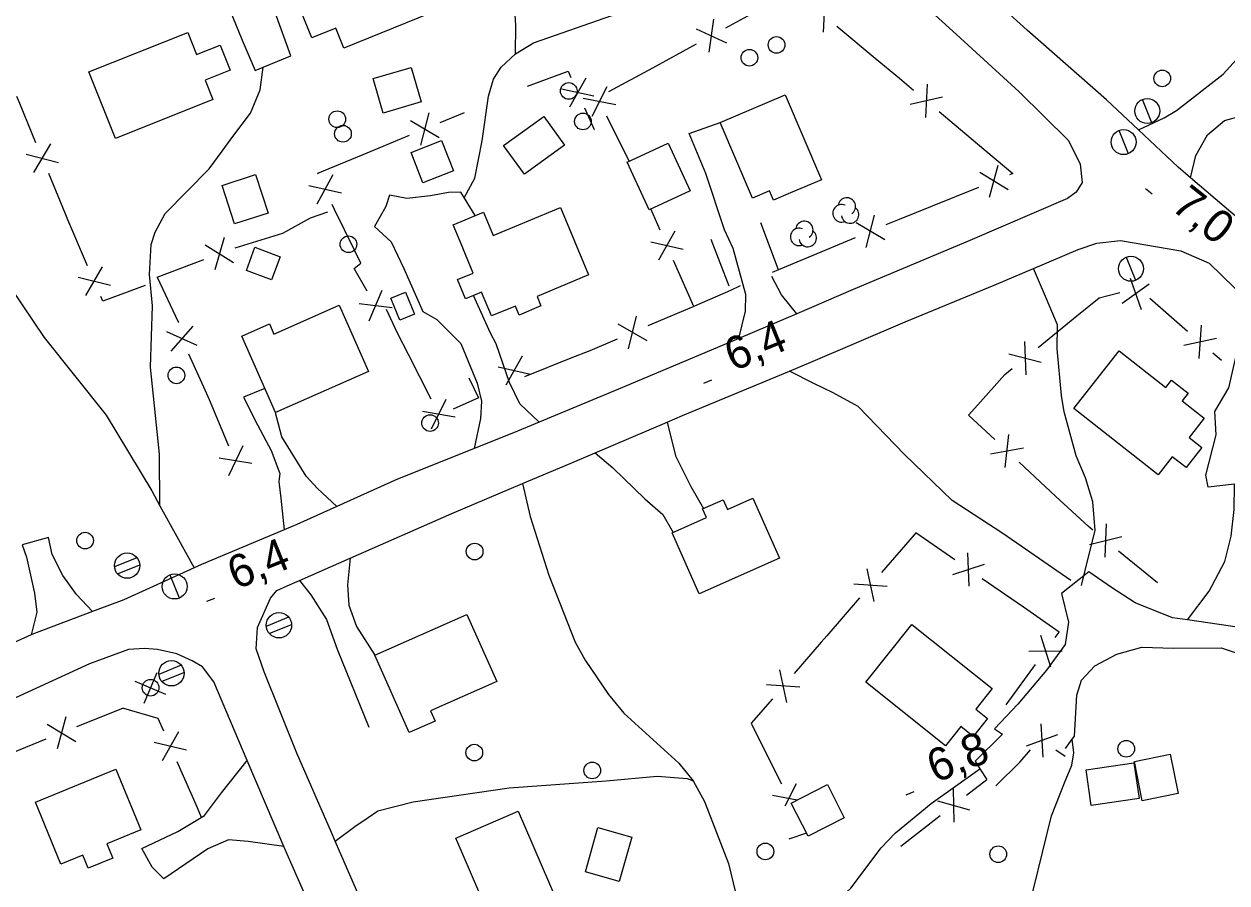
# Model space of a CAD drawing. Extents: x 362852 to 366875, y 5563573 to 5566479.
# Drawn here: x 364014.1 to 364158.5, y 5565067.1 to 5565170.1 of the extents above; entities that cross this region are included whole.
import ezdxf

# ---------------------------------------------------------------- set-up
doc = ezdxf.new("R2010")
doc.units = 0
for name, color, linetype in [('Niveau 19', 7, 'Continuous'), ('Niveau 21', 7, 'Continuous'), ('Niveau 22', 7, 'Continuous'), ('Niveau 3', 7, 'Continuous'), ('Niveau 31', 7, 'Continuous'), ('Niveau 36', 7, 'Continuous'), ('Niveau 37', 7, 'Continuous'), ('Niveau 44', 7, 'Continuous')]:
    doc.layers.add(name, color=color, linetype=linetype)

msp = doc.modelspace()

# ---------------------------------------------------------------- linework, layer by layer
at = {"layer": 'Niveau 19'}
for points in [[(364030.33, 5565182.91), (364033.16, 5565181.85), (364035.02, 5565180.58), (364036.29, 5565179.29), (364037.54, 5565176.67), (364038.08, 5565173.73), (364040.32, 5565168.2), (364041.86, 5565164.58), (364042.81, 5565164.97), (364046.13, 5565166.33), (364044.28, 5565171.52)], [(364147.84, 5565157.46), (364150.92, 5565158.88), (364152.41, 5565159.77), (364158.03, 5565164.14), (364160.41, 5565166.77)], [(364154.09, 5565151.71), (364154.75, 5565154.37), (364156.14, 5565156.85), (364158.19, 5565158.59), (364160.22, 5565159.12), (364161.65, 5565159.27), (364163.04, 5565160.49), (364160.62, 5565162.53), (364161.4, 5565163.35)], [(364099.9, 5565132.43), (364100.69, 5565135.69), (364100.74, 5565137.71), (364099.2, 5565143.21), (364098.16, 5565145.47), (364095.94, 5565152.23), (364093.92, 5565157), (364097.65, 5565158.33)], [(364068.25, 5565147.17), (364066.54, 5565149.97), (364065.06, 5565149.93), (364062.91, 5565149.54), (364060.08, 5565149.23), (364057.99, 5565149.62), (364057.54, 5565148.25), (364056.2, 5565145.86), (364058.2, 5565144.01), (364059.69, 5565140.81), (364061.99, 5565135.65), (364063.68, 5565134.72), (364066.54, 5565131.83), (364068.5, 5565127.09), (364069.01, 5565124.93), (364068.9, 5565122.85), (364068.14, 5565119.23)], [(364106.84, 5565135.4), (364105.01, 5565137.65), (364103.86, 5565139.87)], [(364075.94, 5565122.39), (364073.62, 5565124.6), (364072.38, 5565127.16), (364070.77, 5565131.78), (364070.11, 5565133.08), (364068.06, 5565137.58)], [(364169.24, 5565129.2), (364165.89, 5565127.7), (364164.45, 5565127.11), (364163.02, 5565125.65), (364162.19, 5565122.04), (364162.26, 5565114.76), (364160.28, 5565114.88), (364159.38, 5565114.94), (364156.21, 5565114.6), (364155.94, 5565116.04), (364157.16, 5565120.86), (364157.02, 5565123.67), (364158.71, 5565126.52), (364159.81, 5565131.4), (364160.53, 5565133.95), (364160.91, 5565137.04)], [(364043.03, 5565126.44), (364040.48, 5565125.38), (364042.14, 5565122.06), (364043.78, 5565119.01), (364044.83, 5565116.22), (364044.71, 5565115.29), (364044.93, 5565113.29), (364045.36, 5565109.48)], [(364051.66, 5565112.27), (364049.36, 5565114.45), (364047.98, 5565115.91), (364045.08, 5565120.64), (364044.25, 5565123.69)], [(364091.31, 5565122.4), (364092.31, 5565118.34), (364094.13, 5565114.68), (364095.65, 5565112.05)], [(364082.65, 5565118.71), (364084.78, 5565116.93), (364088.61, 5565113.22), (364090.77, 5565111.33), (364092, 5565109.18)], [(364022.36, 5565099.68), (364020.44, 5565101.74), (364018.78, 5565104), (364017.49, 5565106.54), (364017.05, 5565108.55), (364013.91, 5565107.69), (364014.43, 5565106.19), (364015.37, 5565101.88), (364015.66, 5565099.62), (364014.97, 5565096.89)], [(364053.26, 5565106.07), (364052.95, 5565102.87), (364053.09, 5565100.46), (364054.04, 5565097.88), (364056.22, 5565094.44)], [(364193.33, 5565090.24), (364190.98, 5565090.32), (364189.54, 5565090.65), (364186.03, 5565091.47), (364178.96, 5565093.7), (364173.42, 5565095.05), (364165.08, 5565096.96), (364158.89, 5565097.93), (364153.74, 5565098.68), (364151.93, 5565098.95), (364147.44, 5565100.71), (364144.63, 5565102.56), (364141.88, 5565104.43), (364138.6, 5565101.86), (364139.45, 5565098.43), (364139.06, 5565095.75), (364136.81, 5565092.65), (364133.37, 5565088.59), (364130.58, 5565085.63), (364131.54, 5565084.96), (364128.24, 5565081.73), (364128.82, 5565080.84), (364129.65, 5565079.56)], [(364047.2, 5565103.4), (364048.53, 5565101.69), (364050.43, 5565098.75), (364051.72, 5565095.19), (364055.49, 5565085.83)], [(364139.09, 5565083.25), (364139.88, 5565084.36), (364140.16, 5565084.75), (364140.46, 5565089.64), (364141.01, 5565091.46), (364142.62, 5565093.18), (364145.25, 5565094.56), (364148.27, 5565095.42), (364152.06, 5565095.29), (364157.76, 5565095.34), (364166.76, 5565092.34), (364180.59, 5565088.83), (364187.16, 5565086.77), (364189.66, 5565085.67), (364194.22, 5565083.12), (364197.22, 5565081.17)], [(364045.3, 5565071.49), (364041.03, 5565072.1), (364038.67, 5565072.3), (364036.18, 5565071.22), (364030.91, 5565067.62), (364029.51, 5565069.02), (364028.28, 5565071.27), (364032.59, 5565073.31), (364035.78, 5565075.21), (364037.81, 5565077.95), (364040.9, 5565081.84)]]:
    msp.add_lwpolyline(points, dxfattribs=at)
at = {"layer": 'Niveau 21'}
for points in [[(364117.4, 5565176.73), (364126.01, 5565168.87), (364133.53, 5565162.01), (364139.44, 5565156.18), (364140.85, 5565153.32), (364141.1, 5565151.14), (364140.38, 5565149.97), (364139.32, 5565149.22), (364127.62, 5565144.2), (364113.6, 5565138.3), (364106.84, 5565135.4), (364099.9, 5565132.43), (364085.93, 5565126.54), (364075.94, 5565122.39), (364072.87, 5565121.12), (364058.94, 5565115.56), (364051.66, 5565112.27), (364046.88, 5565110.11), (364045.36, 5565109.48), (364035.44, 5565105.33), (364034.56, 5565104.93), (364026.1, 5565101.09), (364022.36, 5565099.68), (364015.07, 5565096.94), (364014.97, 5565096.89)], [(364161.9, 5565145.07), (364154.09, 5565151.71), (364152.6, 5565152.98), (364147.84, 5565157.46), (364144.01, 5565161.06), (364134.51, 5565169.42), (364126.91, 5565176.33)], [(364047.2, 5565103.4), (364053.26, 5565106.07), (364065.45, 5565111.44), (364073.94, 5565115.02), (364079.68, 5565117.44), (364082.65, 5565118.71), (364091.31, 5565122.4), (364093.15, 5565123.18), (364105.98, 5565128.53), (364108.53, 5565129.59), (364119.85, 5565134.42), (364130.54, 5565138.84), (364135.26, 5565140.83), (364140.6, 5565143.09), (364142.84, 5565143.88), (364145.71, 5565144.18), (364152.93, 5565142.95), (364156.34, 5565141.47), (364160.91, 5565137.04)], [(364076.64, 5565013.12), (364074.62, 5565017.79), (364070.1, 5565028.61), (364065.41, 5565040.22), (364061.55, 5565049.19), (364059.97, 5565052.86), (364057.47, 5565058.45), (364055.09, 5565063.79), (364051.48, 5565072.13), (364051.02, 5565073.18), (364046.88, 5565082.7), (364042.96, 5565092.44), (364041.99, 5565095.2), (364042.14, 5565097.76), (364043.7, 5565101.27), (364044.45, 5565102.2), (364045.71, 5565102.78), (364047.2, 5565103.4)], [(364014.97, 5565096.89), (364004.58, 5565092.2), (363993.89, 5565087.69), (363989.6, 5565085.91), (363982.47, 5565082.95), (363972.35, 5565078.72), (363969.55, 5565077.55), (363966.87, 5565076.45), (363954.9, 5565071.52), (363942.22, 5565066.06), (363940.98, 5565065.54), (363935.86, 5565063.39), (363928.42, 5565060.25), (363915.63, 5565054.66), (363903.7, 5565049.52), (363899.8, 5565047.93), (363890.84, 5565044.27), (363888.1, 5565044.09), (363885.47, 5565045.51), (363884.66, 5565046.43), (363883.7, 5565047.85)], [(364070.9, 5565011.01), (364067.4, 5565020.3), (364061.76, 5565033.41), (364059.17, 5565039.33), (364056.61, 5565045.17), (364051.68, 5565057.14), (364048.11, 5565065.15), (364045.85, 5565070.21), (364045.3, 5565071.49), (364040.9, 5565081.84), (364036.89, 5565091.26), (364035.53, 5565093.07), (364034.32, 5565093.76), (364032.47, 5565094.63), (364030.15, 5565095.12), (364028.6, 5565095.24), (364026.65, 5565095.13), (364021.99, 5565093.4), (364010.11, 5565087.96)]]:
    msp.add_lwpolyline(points, dxfattribs=at)
at = {"layer": 'Niveau 22'}
for points in [[(364073.11, 5565166.57), (364073.14, 5565170.02), (364072.77, 5565175.59), (364071.71, 5565179.29), (364067.79, 5565187.16), (364064.84, 5565192.28), (364063.77, 5565193.53), (364061.43, 5565195.61)], [(364066.96, 5565149.28), (364068.23, 5565151.67), (364069.09, 5565156.15), (364069.87, 5565161.48), (364070.47, 5565163.54), (364071.38, 5565164.98), (364073.11, 5565166.57), (364075.26, 5565167.88), (364084.68, 5565171.15), (364087.7, 5565173.39), (364090.41, 5565175.63)], [(363993.59, 5565168.04), (363995.67, 5565166.21), (363997.93, 5565161.8), (363998.93, 5565159.96), (364005.68, 5565149.03), (364011.28, 5565140.4), (364016.53, 5565132.54), (364024, 5565123.22), (364029.46, 5565114.17), (364030.44, 5565112.37), (364032.47, 5565108.67), (364034.56, 5565104.93)], [(364030.44, 5565112.37), (364030.4, 5565118.54), (364029.3, 5565129), (364029.55, 5565136.36), (364029.18, 5565140.12), (364029.4, 5565143.72), (364029.87, 5565145.16), (364031.08, 5565147.41), (364036.33, 5565152.76), (364037.89, 5565154.9), (364039.2, 5565156.66), (364041.3, 5565159.45), (364042.48, 5565162.25), (364042.81, 5565164.97)], [(364141.03, 5565102.8), (364141.84, 5565106.23), (364142.66, 5565109.39), (364142.38, 5565112.84), (364141.5, 5565115.73), (364140.38, 5565118.37), (364138.92, 5565123.62), (364138.61, 5565125.61), (364138.08, 5565131.18), (364138.15, 5565134.08), (364136.7, 5565137.46), (364135.26, 5565140.83)], [(364139.73, 5565103.42), (364131.57, 5565109.04), (364125.49, 5565113.02), (364119.78, 5565118.5), (364114.22, 5565124.26), (364111.21, 5565125.93), (364108.89, 5565127.04), (364105.98, 5565128.53)], [(364073.94, 5565115.02), (364074.85, 5565111.09), (364077.11, 5565104.04), (364080.28, 5565096), (364081.46, 5565093.86), (364084.25, 5565089.75), (364086.1, 5565087.51), (364092.68, 5565081.49), (364094.4, 5565079.39), (364095.79, 5565076.89), (364098.65, 5565069.47), (364100.61, 5565061.36), (364100.88, 5565060.77), (364104.18, 5565053.64), (364107.33, 5565048.66), (364107.97, 5565047.65), (364111.46, 5565044.94)], [(364153.74, 5565098.68), (364156.34, 5565102.11), (364158.22, 5565105.67), (364158.98, 5565108.73), (364159.33, 5565111.94), (364159.38, 5565114.94)], [(364133.23, 5565059.43), (364135.27, 5565066.38), (364137.4, 5565075.17), (364138.97, 5565079.16), (364139.86, 5565081.28), (364140.08, 5565082.74), (364139.88, 5565084.36)], [(364100.88, 5565060.77), (364102.92, 5565060.75), (364104.96, 5565061.08), (364108.25, 5565062.41), (364110.46, 5565063.88), (364113.33, 5565066.53), (364116.98, 5565071.34), (364118.71, 5565073.14), (364122.98, 5565076.67), (364128.82, 5565080.84)], [(364051.48, 5565072.13), (364053.81, 5565073.92), (364055.41, 5565074.97), (364056.59, 5565075.77), (364060.84, 5565076.86), (364072.34, 5565078.55), (364084, 5565079.37), (364090.09, 5565079.95), (364093.69, 5565079.68), (364094.4, 5565079.39)]]:
    msp.add_lwpolyline(points, dxfattribs=at)
at = {"layer": 'Niveau 3'}
for p, q in [((364148.68, 5565150.41), (364149.5, 5565149.76)), ((364095.68, 5565127.08), (364096.66, 5565127.47)), ((364036.05, 5565100.91), (364037.01, 5565101.3)), ((364119.98, 5565077.72), (364120.94, 5565078.11))]:
    msp.add_line(p, q, dxfattribs=at)
at = {"layer": 'Niveau 31'}
for points in [[(364050.22, 5565172.88), (364049.25, 5565175.25), (364061.1, 5565180.05), (364064.35, 5565172.03), (364052.51, 5565167.24), (364051.53, 5565169.64), (364048.65, 5565168.48), (364047.34, 5565171.71), (364050.22, 5565172.88)], [(364035.87, 5565163.4), (364036.79, 5565161.09), (364025.09, 5565156.42), (364021.9, 5565164.4), (364033.77, 5565169.14), (364034.84, 5565166.47), (364037.67, 5565167.6), (364038.87, 5565164.6), (364035.87, 5565163.4)], [(364061.78, 5565160.79), (364057.23, 5565159.47), (364056.02, 5565163.6), (364060.57, 5565164.92), (364061.78, 5565160.79)], [(364097.65, 5565158.33), (364105.45, 5565161.66), (364109.8, 5565151.47), (364106.1, 5565149.89), (364104.07, 5565149.03), (364103.59, 5565150.14), (364101.52, 5565149.26), (364097.65, 5565158.33)], [(364078.99, 5565155.6), (364074.17, 5565152.12), (364071.67, 5565155.59), (364076.49, 5565159.07), (364078.99, 5565155.6)], [(364064.24, 5565156.17), (364065.66, 5565152.52), (364061.99, 5565151.1), (364060.58, 5565154.75), (364064.24, 5565156.17)], [(364091.41, 5565155.85), (364094.04, 5565150.13), (364089.12, 5565147.86), (364086.48, 5565153.58), (364091.41, 5565155.85)], [(364041.92, 5565152.08), (364043.42, 5565147.47), (364039.4, 5565146.16), (364037.9, 5565150.77), (364041.92, 5565152.08)], [(364068.04, 5565140.28), (364066.82, 5565143.19), (364066.78, 5565143.3), (364065.62, 5565146.07), (364069.25, 5565147.58), (364070.43, 5565144.76), (364078.5, 5565148.14), (364081.88, 5565140.05), (364075.69, 5565137.46), (364076.16, 5565136.33), (364073.55, 5565135.24), (364073.1, 5565136.32), (364070.24, 5565135.13), (364069.04, 5565137.99), (364067.12, 5565137.19), (364066.16, 5565139.49), (364068.04, 5565140.28)], [(364040.81, 5565140.6), (364041.84, 5565143.37), (364044.86, 5565142.24), (364043.83, 5565139.47), (364040.81, 5565140.6)], [(364058.15, 5565137.26), (364059.92, 5565137.98), (364060.99, 5565135.36), (364059.22, 5565134.64), (364058.15, 5565137.26)], [(364044.12, 5565132.94), (364051.95, 5565136.41), (364055.45, 5565128.49), (364044.3, 5565123.56), (364040.26, 5565132.7), (364043.57, 5565134.17), (364044.12, 5565132.94)], [(364150.2, 5565116.09), (364140.1, 5565124.02), (364145.52, 5565130.94), (364151.13, 5565126.54), (364151.83, 5565127.44), (364153.82, 5565125.88), (364153.1, 5565124.97), (364155.75, 5565122.89), (364153.93, 5565120.56), (364155.45, 5565119.36), (364153.56, 5565116.95), (364151.91, 5565118.25), (364150.2, 5565116.09)], [(364104.77, 5565106.08), (364095.13, 5565101.81), (364091.88, 5565109.13), (364096.01, 5565110.96), (364095.54, 5565112.01), (364098, 5565113.09), (364098.52, 5565111.92), (364101.58, 5565113.28), (364104.77, 5565106.08)], [(364063.45, 5565086.54), (364060.34, 5565085.16), (364056.22, 5565094.44), (364067.27, 5565099.34), (364070.85, 5565091.29), (364062.91, 5565087.76), (364063.45, 5565086.54)], [(364126.52, 5565085.89), (364124.69, 5565083.6), (364115.13, 5565091.23), (364120.64, 5565098.14), (364130.28, 5565090.45), (364128.32, 5565087.99), (364129.73, 5565086.86), (364128.01, 5565084.7), (364126.52, 5565085.89)], [(364151.66, 5565082.58), (364152.62, 5565077.85), (364148.31, 5565076.97), (364147.36, 5565081.7), (364151.66, 5565082.58)], [(364015.49, 5565076.83), (364025.15, 5565080.79), (364028.14, 5565073.49), (364024.07, 5565071.82), (364024.77, 5565070.12), (364021.81, 5565068.91), (364021.17, 5565070.45), (364018.55, 5565069.38), (364015.49, 5565076.83)], [(364141.57, 5565080.72), (364147.3, 5565081.55), (364147.92, 5565077.26), (364142.19, 5565076.43), (364141.57, 5565080.72)], [(364106.17, 5565076.7), (364110.52, 5565078.93), (364112.54, 5565074.96), (364108.2, 5565072.74), (364106.17, 5565076.7)], [(364071.45, 5565059.7), (364065.93, 5565072.51), (364073.43, 5565075.74), (364078.93, 5565062.96), (364077.14, 5565062.19), (364077.85, 5565060.53), (364075.01, 5565059.31), (364074.31, 5565060.94), (364071.45, 5565059.7)], [(364087.06, 5565072.63), (364085.55, 5565067.33), (364081.49, 5565068.49), (364083, 5565073.79), (364087.06, 5565072.63)]]:
    msp.add_lwpolyline(points, dxfattribs=at)
at = {"layer": 'Niveau 36'}
for p, q in [((364149.47, 5565158.3), (364148.35, 5565161.08)), ((364146.64, 5565154.58), (364145.52, 5565157.36)), ((364147.52, 5565139.37), (364146.4, 5565142.15)), ((364027.67, 5565106.13), (364024.99, 5565105.04)), ((364025.33, 5565104.19), (364028.02, 5565105.28)), ((364032.77, 5565101.28), (364031.65, 5565104.06)), ((364045.88, 5565099), (364043.2, 5565097.91)), ((364043.54, 5565097.06), (364046.23, 5565098.15)), ((364028.54, 5565088.69), (364030.09, 5565092.36)), ((364032.97, 5565093.24), (364030.29, 5565092.15)), ((364030.63, 5565091.3), (364033.32, 5565092.39)), ((364031.15, 5565089.75), (364027.48, 5565091.3))]:
    msp.add_line(p, q, dxfattribs=at)
for centre, radius in [((364104.42, 5565167.63), 1), ((364101.17, 5565166.1), 1), ((364150.71, 5565163.62), 1), ((364079.49, 5565162.11), 1), ((364148.91, 5565159.71), 1.5), ((364051.71, 5565158.73), 1), ((364081.19, 5565158.46), 1), ((364052.4, 5565156.98), 1), ((364146.07, 5565155.98), 1.5), ((364053.06, 5565143.73), 1), ((364146.95, 5565140.79), 1.5), ((364032.41, 5565128.01), 1), ((364062.85, 5565122.29), 1), ((364021.45, 5565108.19), 1), ((364026.5, 5565105.19), 1.52), ((364068.2, 5565106.88), 1), ((364032.2, 5565102.69), 1.5), ((364044.72, 5565098.04), 1.52), ((364031.82, 5565092.28), 1.52), ((364029.31, 5565090.55), 1), ((364068.16, 5565082.77), 1), ((364146.39, 5565083.23), 1), ((364082.31, 5565080.63), 1), ((364103.08, 5565070.91), 1), ((364131.03, 5565070.58), 1)]:
    msp.add_circle(centre, radius, dxfattribs=at)
at = {"layer": 'Niveau 37'}
for p, q in [((364110.22, 5565173.17), (364110.01, 5565169.18)), ((364098.34, 5565169.69), (364103.61, 5565172.56)), ((364096.87, 5565170.71), (364096.3, 5565166.75)), ((364094.76, 5565169.56), (364098.4, 5565167.9)), ((364111.66, 5565169.9), (364116.27, 5565166.06)), ((364089.56, 5565164.9), (364094.83, 5565167.78)), ((364084.29, 5565162.03), (364089.56, 5565164.9)), ((364081.53, 5565163.66), (364079.6, 5565160.16)), ((364082.52, 5565161.47), (364078.61, 5565162.34)), ((364082.29, 5565159.08), (364084.1, 5565162.65)), ((364122.51, 5565162.92), (364122.29, 5565158.92)), ((364081.23, 5565161.23), (364085.16, 5565160.5)), ((364081.39, 5565160.08), (364082.55, 5565157.51)), ((364124.35, 5565161.38), (364120.45, 5565160.47)), ((364062.71, 5565159.5), (364061.72, 5565155.62)), ((364064.06, 5565158.33), (364066.99, 5565159.54)), ((364086.74, 5565153.7), (364084.08, 5565159.08)), ((364123.94, 5565159.64), (364128.53, 5565155.78)), ((364060.49, 5565158.58), (364063.93, 5565156.54)), ((364015.31, 5565152.32), (364017.35, 5565155.76)), ((364054.82, 5565154.51), (364060.37, 5565156.8)), ((364014.39, 5565154.54), (364018.27, 5565153.55)), ((364129.99, 5565149.36), (364131.02, 5565153.23)), ((364049.32, 5565148.57), (364051.23, 5565152.08)), ((364132.22, 5565150.26), (364128.8, 5565152.33)), ((364048.32, 5565150.76), (364052.23, 5565149.9)), ((364128.65, 5565150.54), (364123.09, 5565148.3)), ((364090.45, 5565145.42), (364089.33, 5565147.96)), ((364115.19, 5565143.33), (364116.18, 5565147.21)), ((364021.76, 5565141.15), (364019.4, 5565146.66)), ((364104.64, 5565140.67), (364102.55, 5565146.3)), ((364117.41, 5565144.26), (364113.96, 5565146.29)), ((364038.13, 5565144.53), (364037.01, 5565140.68)), ((364090.29, 5565141.85), (364092.24, 5565145.34)), ((364096.54, 5565144.34), (364098.7, 5565138.74)), ((364113.84, 5565144.5), (364108.3, 5565142.19)), ((364035.88, 5565143.68), (364039.26, 5565141.53)), ((364089.32, 5565144.04), (364093.22, 5565143.14)), ((364030.09, 5565139.78), (364035.7, 5565141.9)), ((364094.5, 5565136.28), (364092.07, 5565141.77)), ((364021.56, 5565137.57), (364023.56, 5565141.04)), ((364020.62, 5565139.78), (364024.5, 5565138.84)), ((364149.15, 5565138.94), (364145.89, 5565136.63)), ((364146.87, 5565139.67), (364148.18, 5565135.89)), ((364055.56, 5565134.54), (364057.11, 5565138.23)), ((364149.2, 5565137.25), (364153.74, 5565133.32)), ((364054.35, 5565136.62), (364058.32, 5565136.16)), ((364094.5, 5565136.28), (364088.98, 5565133.93)), ((364088.88, 5565132.15), (364085.41, 5565134.15)), ((364086.67, 5565131.2), (364087.62, 5565135.09)), ((364135.8, 5565131.35), (364140.46, 5565135.13)), ((364034.89, 5565131.57), (364031.25, 5565133.24)), ((364034.38, 5565133.92), (364031.76, 5565130.89)), ((364155.38, 5565134.01), (364155.11, 5565130.02)), ((364134.17, 5565132.08), (364134.32, 5565128.09)), ((364157.2, 5565132.44), (364153.29, 5565131.59)), ((364062.98, 5565125.16), (364060.26, 5565130.51)), ((364071.99, 5565126.86), (364073.94, 5565130.35)), ((364079.76, 5565130.05), (364074.19, 5565127.82)), ((364132.3, 5565130.57), (364136.18, 5565129.6)), ((364156.76, 5565130.71), (364157.8, 5565129.81)), ((364071.01, 5565129.05), (364074.91, 5565128.16)), ((364036.33, 5565125.1), (364038.66, 5565119.57)), ((364063.02, 5565121.58), (364064.78, 5565125.17)), ((364061.93, 5565123.72), (364065.87, 5565123.04)), ((364131.87, 5565116.95), (364132.28, 5565120.93)), ((364040.38, 5565119.57), (364038.65, 5565115.96)), ((364130.11, 5565118.58), (364134.04, 5565119.3)), ((364041.48, 5565117.44), (364037.54, 5565118.09)), ((364137.94, 5565113.5), (364133.54, 5565117.58)), ((364143.85, 5565106.2), (364144.01, 5565110.2)), ((364120.94, 5565108.89), (364117.01, 5565104.35)), ((364141.99, 5565107.72), (364145.87, 5565108.68)), ((364127.54, 5565102.74), (364127.39, 5565106.74)), ((364150.12, 5565103.14), (364145.47, 5565106.93)), ((364125.57, 5565104.11), (364129.36, 5565105.37)), ((364116.12, 5565100.89), (364115.28, 5565104.8)), ((364117.7, 5565102.7), (364113.71, 5565102.98)), ((364134.04, 5565100.19), (364129.11, 5565103.6)), ((364114.39, 5565101.33), (364110.46, 5565096.79)), ((364136.09, 5565096.86), (364137.28, 5565093.04)), ((364134.68, 5565094.92), (364138.68, 5565094.99)), ((364105.65, 5565088.79), (364104.8, 5565092.7)), ((364131.99, 5565088.48), (364135.51, 5565093.34)), ((364107.22, 5565090.61), (364103.23, 5565090.89)), ((364019.14, 5565087.07), (364018.1, 5565083.21)), ((364016.91, 5565086.18), (364020.33, 5565084.1)), ((364032.66, 5565085.27), (364030.69, 5565081.79)), ((364136.14, 5565086.21), (364136.36, 5565082.22)), ((364011.2, 5565082.16), (364016.77, 5565084.4)), ((364033.62, 5565083.07), (364029.73, 5565083.98)), ((364102.31, 5565084.4), (364105, 5565079.04)), ((364138.13, 5565084.88), (364134.36, 5565083.55)), ((364137.92, 5565083.1), (364139.06, 5565082.34)), ((364032.48, 5565081.69), (364034.89, 5565076.2)), ((364127.23, 5565077.67), (364129.65, 5565079.56)), ((364106.78, 5565079.04), (364105.43, 5565076.33)), ((364125.61, 5565078.44), (364125.69, 5565074.44)), ((364106.9, 5565077.07), (364103.92, 5565077.61)), ((364123.72, 5565076.97), (364127.58, 5565075.92)), ((364034.89, 5565076.2), (364035.4, 5565075.04)), ((364119.34, 5565071.53), (364124.07, 5565075.22)), ((364108.01, 5565073.1), (364105.91, 5565072.39))]:
    msp.add_line(p, q, dxfattribs=at)
for points in [[(364116.27, 5565166.06), (364119.18, 5565163.63), (364120.87, 5565162.21)], [(364074.55, 5565162.7), (364079.41, 5565164.48), (364079.75, 5565163.73)], [(364015.56, 5565155.89), (364013.61, 5565160.6), (364013.26, 5565161.43)], [(364128.53, 5565155.78), (364132.78, 5565152.21), (364132.36, 5565152.04)], [(364049.44, 5565152.15), (364049.39, 5565152.26), (364054.82, 5565154.51)], [(364019.4, 5565146.66), (364019.06, 5565147.44), (364017.09, 5565152.2)], [(364053.73, 5565143.12), (364051.37, 5565147.91), (364051.1, 5565148.51)], [(364045.18, 5565145.06), (364048.51, 5565146.9), (364050.59, 5565147.63)], [(364123.09, 5565148.3), (364119.15, 5565146.71), (364117.53, 5565146.04)], [(364039.45, 5565143.29), (364045.18, 5565145.06), (364045.18, 5565145.06)], [(364055.32, 5565138.12), (364053.74, 5565140.82), (364054.54, 5565141.46), (364053.73, 5565143.12)], [(364108.3, 5565142.19), (364104.64, 5565140.67), (364103.89, 5565140.36)], [(364028.65, 5565138.78), (364023.58, 5565136.92), (364023.34, 5565137.47)], [(364030.09, 5565139.78), (364032.63, 5565134.44), (364032.65, 5565134.36)], [(364100.07, 5565138.73), (364098.91, 5565138.19), (364094.59, 5565136.32), (364094.58, 5565136.31)], [(364140.46, 5565135.13), (364143.14, 5565137.3), (364145.61, 5565137.93)], [(364060.26, 5565130.51), (364058.96, 5565133.05), (364057.62, 5565135.9)], [(364085.3, 5565132.36), (364082.03, 5565130.96), (364079.76, 5565130.05)], [(364033.86, 5565130.57), (364035.68, 5565126.63), (364036.33, 5565125.1)], [(364128.56, 5565124.49), (364131.8, 5565128.11), (364132.69, 5565128.83)], [(364067.51, 5565127.72), (364068.67, 5565125.32), (364065.63, 5565123.95)], [(364130.6, 5565120.3), (364127.44, 5565123.23), (364128.56, 5565124.49)], [(364142.37, 5565109.46), (364141.81, 5565109.92), (364137.94, 5565113.5)], [(364125.82, 5565105.88), (364121.14, 5565109.12), (364120.94, 5565108.89)], [(364137.86, 5565096.58), (364138.32, 5565097.22), (364134.04, 5565100.19)], [(364110.46, 5565096.79), (364109.79, 5565096.01), (364106.54, 5565092.25)], [(364020.48, 5565085.89), (364025.98, 5565088.1), (364026.05, 5565088.08)], [(364026.05, 5565088.08), (364030.2, 5565086.9), (364030.88, 5565085.36)], [(364103.92, 5565089.23), (364101.37, 5565086.29), (364102.31, 5565084.4)], [(364130.73, 5565078.8), (364133.66, 5565081.65), (364134.9, 5565083.11)]]:
    msp.add_lwpolyline(points, dxfattribs=at)
at = {"layer": 'Niveau 44'}
for centre, start, end in [((364112.86, 5565148.26), 304.3592, 171.8163), ((364112.22, 5565147.44), 66.2054, 291.894), ((364113.25, 5565147.29), 189.0269, 51.7112), ((364107.13, 5565144.61), 66.2054, 291.894), ((364107.76, 5565145.44), 304.3592, 171.8163), ((364108.16, 5565144.47), 189.0269, 51.7112)]:
    msp.add_arc(centre, 1.05, start, end, dxfattribs=at)

# ---------------------------------------------------------------- texts
at = {"layer": 'Niveau 3'}
for s, rotation, p in [('7,0  ', 321.6788, (364151.6, 5565148.02)), ('6,4  ', 22.09, (364099.2, 5565128.45)), ('6,4  ', 22.09, (364039.56, 5565102.27)), ('6,8  ', 22.09, (364123.49, 5565079.08))]:
    msp.add_text(s, height=3.93, rotation=rotation, dxfattribs=at).set_placement(p)

doc.saveas('drawing.dxf')
